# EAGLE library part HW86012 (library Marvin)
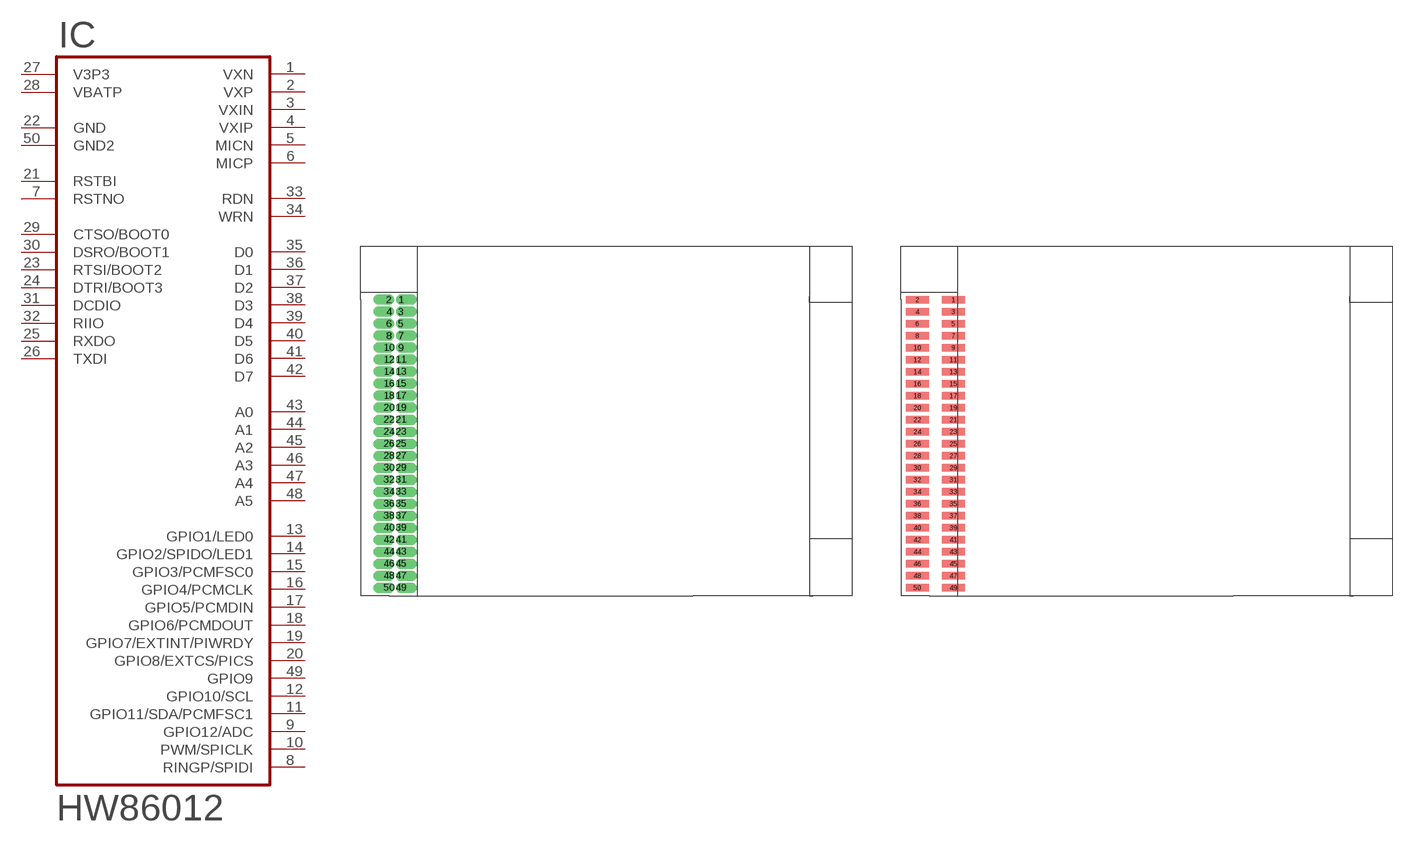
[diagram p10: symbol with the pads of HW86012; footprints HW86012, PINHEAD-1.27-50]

Designator prefix IC

## HW86012D  [HW86012]
1  VXN
2  VXP
3  VXIN
4  VXIP
5  MICN
6  MICP
7  RSTNO  out
8  RINGP/SPIDI
9  GPIO12/ADC
10  PWM/SPICLK
11  GPIO11/SDA/PCMFSC1
12  GPIO10/SCL
13  GPIO1/LED0
14  GPIO2/SPIDO/LED1
15  GPIO3/PCMFSC0
16  GPIO4/PCMCLK
17  GPIO5/PCMDIN
18  GPIO6/PCMDOUT
19  GPIO7/EXTINT/PIWRDY
20  GPIO8/EXTCS/PICS
21  RSTBI  in
22  GND  pwr
23  RTSI/BOOT2
24  DTRI/BOOT3
25  RXDO  out
26  TXDI  in
27  V3P3  pwr
28  VBATP  pwr
29  CTSO/BOOT0
30  DSRO/BOOT1
31  DCDIO
32  RIIO
33  RDN
34  WRN
35  D0
36  D1
37  D2
38  D3
39  D4
40  D5
41  D6
42  D7
43  A0
44  A1
45  A2
46  A3
47  A4
48  A5
49  GPIO9
50  GND2  pwr

## HW86012S  [PINHEAD-1.27-50]
Pads as for HW86012

## Footprint HW86012 (pad centres in mm)
drill 0.6 pad 0.85 offset: 1 1.273,-0.002; 2 0.003,-0.002; 3 1.273,-1.272; 4 0.003,-1.272; 5 1.273,-2.542; 6 0.003,-2.542; 7 1.273,-3.812; 8 0.003,-3.812; 9 1.273,-5.082; 10 0.003,-5.082; 11 1.273,-6.352; 12 0.003,-6.352; 13 1.273,-7.622; 14 0.003,-7.622; 15 1.273,-8.892; 16 0.003,-8.892; 17 1.273,-10.162; 18 0.003,-10.162; 19 1.273,-11.432; 20 0.003,-11.432; 21 1.273,-12.702; 22 0.003,-12.702; 23 1.273,-13.972; 24 0.003,-13.972; 25 1.273,-15.242; 26 0.003,-15.242; 27 1.273,-16.512; 28 0.003,-16.512; 29 1.273,-17.782; 30 0.003,-17.782; 31 1.273,-19.052; 32 0.003,-19.052; 33 1.273,-20.322; 34 0.003,-20.322; 35 1.273,-21.592; 36 0.003,-21.592; 37 1.273,-22.862; 38 0.003,-22.862; 39 1.273,-24.132; 40 0.003,-24.132; 41 1.273,-25.402; 42 0.003,-25.402; 43 1.273,-26.672; 44 0.003,-26.672; 45 1.273,-27.942; 46 0.003,-27.942; 47 1.273,-29.212; 48 0.003,-29.212; 49 1.273,-30.482; 50 0.003,-30.482

## Footprint PINHEAD-1.27-50 (pad centres in mm)
smd 2.4 x 0.76: 1 2.54,0; 2 -1.27,0; 3 2.54,-1.27; 4 -1.27,-1.27; 5 2.54,-2.54; 6 -1.27,-2.54; 7 2.54,-3.81; 8 -1.27,-3.81; 9 2.54,-5.08; 10 -1.27,-5.08; 11 2.54,-6.35; 12 -1.27,-6.35; 13 2.54,-7.62; 14 -1.27,-7.62; 15 2.54,-8.89; 16 -1.27,-8.89; 17 2.54,-10.16; 18 -1.27,-10.16; 19 2.54,-11.43; 20 -1.27,-11.43; 21 2.54,-12.7; 22 -1.27,-12.7; 23 2.54,-13.97; 24 -1.27,-13.97; 25 2.54,-15.24; 26 -1.27,-15.24; 27 2.54,-16.51; 28 -1.27,-16.51; 29 2.54,-17.78; 30 -1.27,-17.78; 31 2.54,-19.05; 32 -1.27,-19.05; 33 2.54,-20.32; 34 -1.27,-20.32; 35 2.54,-21.59; 36 -1.27,-21.59; 37 2.54,-22.86; 38 -1.27,-22.86; 39 2.54,-24.13; 40 -1.27,-24.13; 41 2.54,-25.4; 42 -1.27,-25.4; 43 2.54,-26.67; 44 -1.27,-26.67; 45 2.54,-27.94; 46 -1.27,-27.94; 47 2.54,-29.21; 48 -1.27,-29.21; 49 2.54,-30.48; 50 -1.27,-30.48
